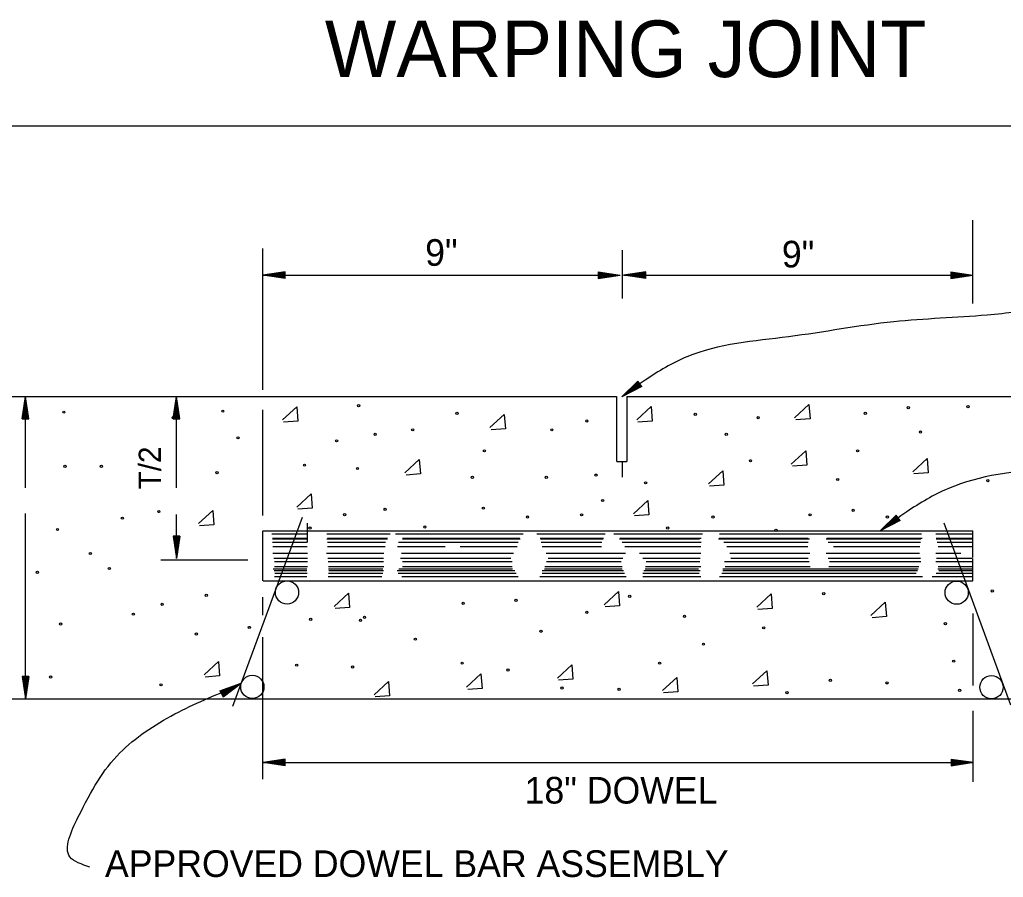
# Model space of a CAD drawing. Extents: x 1375738 to 1375905, y 380661 to 380875.
# Drawn here: x 1375749.18 to 1375765.86, y 380802.04 to 380816.58 of the extents above; entities that cross this region are included whole.
import ezdxf

# ---------------------------------------------------------------- set-up
doc = ezdxf.new("R2010")
doc.units = 0
doc.layers.add('R_Border', color=7, linetype='Continuous')
doc.layers.add('R_Draft', color=7, linetype='Continuous')

msp = doc.modelspace()

# ---------------------------------------------------------------- linework, layer by layer
at = {"layer": 'R_Border'}
msp.add_line((1375744.419, 380814.777), (1375786.095, 380814.777), dxfattribs=at)
at = {"layer": 'R_Draft'}
for p, q in [((1375765.343, 380811.767), (1375765.343, 380813.18)), ((1375753.306, 380810.302), (1375753.306, 380812.699)), ((1375759.401, 380811.851), (1375759.401, 380812.671)), ((1375753.682, 380812.303), (1375753.306, 380812.247)), ((1375753.682, 380812.19), (1375753.682, 380812.303)), ((1375758.988, 380812.303), (1375759.364, 380812.247)), ((1375758.988, 380812.303), (1375758.988, 380812.19)), ((1375759.797, 380812.303), (1375759.42, 380812.247)), ((1375759.797, 380812.303), (1375759.42, 380812.247)), ((1375759.797, 380812.19), (1375759.797, 380812.303)), ((1375759.797, 380812.19), (1375759.797, 380812.303)), ((1375764.966, 380812.303), (1375765.343, 380812.247)), ((1375764.966, 380812.303), (1375764.966, 380812.19)), ((1375753.306, 380812.247), (1375759.364, 380812.247)), ((1375753.682, 380812.19), (1375753.306, 380812.247)), ((1375753.682, 380812.294), (1375753.369, 380812.247)), ((1375753.682, 380812.2), (1375753.369, 380812.247)), ((1375753.682, 380812.284), (1375753.434, 380812.247)), ((1375753.682, 380812.21), (1375753.434, 380812.247)), ((1375753.682, 380812.275), (1375753.496, 380812.247)), ((1375753.682, 380812.219), (1375753.496, 380812.247)), ((1375753.682, 380812.265), (1375753.56, 380812.247)), ((1375753.682, 380812.229), (1375753.56, 380812.247)), ((1375753.682, 380812.255), (1375753.623, 380812.247)), ((1375753.682, 380812.238), (1375753.623, 380812.247)), ((1375758.988, 380812.294), (1375759.301, 380812.247)), ((1375758.988, 380812.284), (1375759.236, 380812.247)), ((1375758.988, 380812.275), (1375759.174, 380812.247)), ((1375758.988, 380812.265), (1375759.11, 380812.247)), ((1375758.988, 380812.255), (1375759.047, 380812.247)), ((1375758.988, 380812.19), (1375759.364, 380812.247)), ((1375758.988, 380812.228), (1375759.11, 380812.247)), ((1375758.988, 380812.21), (1375759.236, 380812.247)), ((1375758.988, 380812.2), (1375759.301, 380812.247)), ((1375758.988, 380812.219), (1375759.174, 380812.247)), ((1375758.988, 380812.238), (1375759.047, 380812.247)), ((1375759.42, 380812.247), (1375765.343, 380812.247)), ((1375759.797, 380812.19), (1375759.42, 380812.247)), ((1375759.797, 380812.19), (1375759.42, 380812.247)), ((1375759.797, 380812.294), (1375759.483, 380812.247)), ((1375759.797, 380812.294), (1375759.483, 380812.247)), ((1375759.797, 380812.2), (1375759.483, 380812.247)), ((1375759.797, 380812.2), (1375759.483, 380812.247)), ((1375759.797, 380812.284), (1375759.548, 380812.247)), ((1375759.797, 380812.284), (1375759.548, 380812.247)), ((1375759.797, 380812.21), (1375759.548, 380812.247)), ((1375759.797, 380812.21), (1375759.548, 380812.247)), ((1375759.797, 380812.275), (1375759.61, 380812.247)), ((1375759.797, 380812.275), (1375759.61, 380812.247)), ((1375759.797, 380812.219), (1375759.61, 380812.247)), ((1375759.797, 380812.219), (1375759.61, 380812.247)), ((1375759.797, 380812.265), (1375759.674, 380812.247)), ((1375759.797, 380812.265), (1375759.674, 380812.247)), ((1375759.797, 380812.229), (1375759.674, 380812.247)), ((1375759.797, 380812.229), (1375759.674, 380812.247)), ((1375759.797, 380812.255), (1375759.738, 380812.247)), ((1375759.797, 380812.255), (1375759.738, 380812.247)), ((1375759.797, 380812.238), (1375759.738, 380812.247)), ((1375759.797, 380812.238), (1375759.738, 380812.247)), ((1375764.966, 380812.294), (1375765.28, 380812.247)), ((1375764.966, 380812.284), (1375765.215, 380812.247)), ((1375764.966, 380812.275), (1375765.153, 380812.247)), ((1375764.966, 380812.265), (1375765.089, 380812.247)), ((1375764.966, 380812.255), (1375765.026, 380812.247)), ((1375764.966, 380812.19), (1375765.343, 380812.247)), ((1375764.966, 380812.228), (1375765.089, 380812.247)), ((1375764.966, 380812.21), (1375765.215, 380812.247)), ((1375764.966, 380812.2), (1375765.28, 380812.247)), ((1375764.966, 380812.219), (1375765.153, 380812.247)), ((1375764.966, 380812.238), (1375765.026, 380812.247)), ((1375759.665, 380810.448), (1375759.392, 380810.183)), ((1375759.731, 380810.356), (1375759.392, 380810.183)), ((1375759.671, 380810.441), (1375759.443, 380810.22)), ((1375759.726, 380810.364), (1375759.443, 380810.22)), ((1375759.676, 380810.432), (1375759.496, 380810.257)), ((1375759.72, 380810.371), (1375759.496, 380810.257)), ((1375759.682, 380810.425), (1375759.547, 380810.294)), ((1375759.714, 380810.379), (1375759.547, 380810.294)), ((1375759.688, 380810.417), (1375759.599, 380810.331)), ((1375759.709, 380810.387), (1375759.599, 380810.331)), ((1375759.693, 380810.409), (1375759.65, 380810.368)), ((1375759.703, 380810.395), (1375759.65, 380810.368)), ((1375759.731, 380810.356), (1375759.665, 380810.448)), ((1375747.021, 380810.189), (1375759.3, 380810.189)), ((1375749.223, 380809.813), (1375749.279, 380810.189)), ((1375749.336, 380809.813), (1375749.279, 380810.189)), ((1375749.279, 380808.642), (1375749.279, 380810.189)), ((1375751.786, 380809.813), (1375751.843, 380810.189)), ((1375751.843, 380808.642), (1375751.843, 380810.189)), ((1375751.9, 380809.813), (1375751.843, 380810.189)), ((1375759.305, 380809.089), (1375759.305, 380810.189)), ((1375759.477, 380810.189), (1375771.466, 380810.189)), ((1375759.479, 380809.089), (1375759.479, 380810.189)), ((1375749.232, 380809.813), (1375749.279, 380810.127)), ((1375749.242, 380809.813), (1375749.279, 380810.062)), ((1375749.251, 380809.813), (1375749.279, 380809.999)), ((1375749.326, 380809.813), (1375749.279, 380810.127)), ((1375749.316, 380809.813), (1375749.279, 380810.062)), ((1375749.307, 380809.813), (1375749.279, 380809.999)), ((1375751.796, 380809.813), (1375751.843, 380810.127)), ((1375751.806, 380809.813), (1375751.843, 380810.062)), ((1375751.815, 380809.813), (1375751.843, 380809.999)), ((1375751.89, 380809.813), (1375751.843, 380810.127)), ((1375751.88, 380809.813), (1375751.843, 380810.062)), ((1375751.871, 380809.813), (1375751.843, 380809.999)), ((1375749.223, 380809.813), (1375749.336, 380809.813)), ((1375749.261, 380809.813), (1375749.279, 380809.935)), ((1375749.27, 380809.813), (1375749.279, 380809.872)), ((1375749.298, 380809.813), (1375749.279, 380809.935)), ((1375749.288, 380809.813), (1375749.279, 380809.872)), ((1375751.786, 380809.813), (1375751.9, 380809.813)), ((1375751.825, 380809.813), (1375751.843, 380809.935)), ((1375751.835, 380809.813), (1375751.843, 380809.872)), ((1375751.862, 380809.813), (1375751.843, 380809.935)), ((1375751.852, 380809.813), (1375751.843, 380809.872)), ((1375753.306, 380808.173), (1375753.306, 380809.964)), ((1375759.305, 380809.089), (1375759.475, 380809.089)), ((1375759.401, 380808.819), (1375759.401, 380809.073)), ((1375749.279, 380805.063), (1375749.279, 380808.203)), ((1375751.843, 380807.442), (1375751.843, 380808.186)), ((1375753.97, 380808.136), (1375752.793, 380804.931)), ((1375764.044, 380808.175), (1375763.77, 380807.911)), ((1375764.05, 380808.168), (1375763.822, 380807.947)), ((1375764.055, 380808.16), (1375763.874, 380807.985)), ((1375764.06, 380808.153), (1375763.925, 380808.021)), ((1375764.066, 380808.145), (1375763.977, 380808.059)), ((1375764.072, 380808.137), (1375764.028, 380808.095)), ((1375764.11, 380808.084), (1375764.044, 380808.175)), ((1375754.06, 380807.72), (1375754.06, 380808.04)), ((1375764.11, 380808.084), (1375763.77, 380807.911)), ((1375764.104, 380808.091), (1375763.822, 380807.947)), ((1375764.098, 380808.099), (1375763.874, 380807.985)), ((1375764.093, 380808.107), (1375763.925, 380808.021)), ((1375764.088, 380808.115), (1375763.977, 380808.059)), ((1375764.082, 380808.122), (1375764.028, 380808.095)), ((1375764.849, 380808.047), (1375765.982, 380804.959)), ((1375751.786, 380807.819), (1375751.843, 380807.442)), ((1375751.9, 380807.819), (1375751.786, 380807.819)), ((1375751.796, 380807.819), (1375751.843, 380807.505)), ((1375751.806, 380807.819), (1375751.843, 380807.57)), ((1375751.815, 380807.819), (1375751.843, 380807.633)), ((1375751.824, 380807.819), (1375751.843, 380807.697)), ((1375751.835, 380807.819), (1375751.843, 380807.759)), ((1375751.9, 380807.819), (1375751.843, 380807.442)), ((1375751.861, 380807.819), (1375751.843, 380807.697)), ((1375751.88, 380807.819), (1375751.843, 380807.57)), ((1375751.89, 380807.819), (1375751.843, 380807.505)), ((1375751.871, 380807.819), (1375751.843, 380807.633)), ((1375751.852, 380807.819), (1375751.843, 380807.759)), ((1375753.306, 380807.066), (1375753.306, 380807.911)), ((1375753.312, 380807.911), (1375765.343, 380807.911)), ((1375753.456, 380807.859), (1375754.056, 380807.859)), ((1375754.392, 380807.859), (1375755.462, 380807.859)), ((1375755.554, 380807.859), (1375757.718, 380807.859)), ((1375757.95, 380807.859), (1375759.109, 380807.859)), ((1375759.258, 380807.859), (1375760.756, 380807.859)), ((1375761.046, 380807.859), (1375764.473, 380807.859)), ((1375764.714, 380807.859), (1375765.341, 380807.859)), ((1375765.343, 380807.461), (1375765.343, 380807.911)), ((1375753.466, 380807.788), (1375754.06, 380807.788)), ((1375753.466, 380807.774), (1375754.06, 380807.774)), ((1375753.466, 380807.717), (1375754.056, 380807.717)), ((1375753.477, 380807.647), (1375754.056, 380807.647)), ((1375754.392, 380807.774), (1375755.42, 380807.774)), ((1375754.399, 380807.788), (1375755.42, 380807.788)), ((1375754.399, 380807.717), (1375755.385, 380807.717)), ((1375754.399, 380807.647), (1375755.378, 380807.647)), ((1375755.59, 380807.647), (1375756.396, 380807.647)), ((1375755.604, 380807.717), (1375757.632, 380807.717)), ((1375755.675, 380807.788), (1375757.66, 380807.788)), ((1375755.675, 380807.774), (1375757.668, 380807.774)), ((1375756.65, 380807.647), (1375757.618, 380807.647)), ((1375758.007, 380807.788), (1375759.081, 380807.788)), ((1375758.014, 380807.774), (1375759.074, 380807.774)), ((1375758.021, 380807.717), (1375759.052, 380807.717)), ((1375758.042, 380807.647), (1375759.046, 380807.647)), ((1375759.35, 380807.774), (1375760.707, 380807.774)), ((1375759.357, 380807.788), (1375760.735, 380807.788)), ((1375759.399, 380807.717), (1375760.735, 380807.717)), ((1375759.441, 380807.647), (1375760.728, 380807.647)), ((1375761.031, 380807.774), (1375762.572, 380807.774)), ((1375761.039, 380807.788), (1375762.551, 380807.788)), ((1375761.123, 380807.717), (1375762.551, 380807.717)), ((1375761.173, 380807.647), (1375762.544, 380807.647)), ((1375762.855, 380807.774), (1375764.459, 380807.774)), ((1375762.869, 380807.788), (1375764.481, 380807.788)), ((1375762.89, 380807.717), (1375764.452, 380807.717)), ((1375762.982, 380807.647), (1375764.445, 380807.647)), ((1375764.721, 380807.788), (1375765.341, 380807.788)), ((1375764.721, 380807.774), (1375765.341, 380807.774)), ((1375764.735, 380807.717), (1375765.341, 380807.717)), ((1375764.756, 380807.647), (1375765.341, 380807.647)), ((1375753.474, 380807.533), (1375754.06, 380807.533)), ((1375754.385, 380807.533), (1375755.357, 380807.533)), ((1375755.653, 380807.533), (1375757.555, 380807.533)), ((1375758.106, 380807.533), (1375759.455, 380807.533)), ((1375759.688, 380807.533), (1375760.728, 380807.533)), ((1375761.222, 380807.533), (1375762.58, 380807.533)), ((1375762.855, 380807.533), (1375764.438, 380807.533)), ((1375764.714, 380807.533), (1375765.138, 380807.533)), ((1375751.576, 380807.418), (1375753.049, 380807.418)), ((1375753.494, 380807.449), (1375754.06, 380807.449)), ((1375753.502, 380807.392), (1375754.063, 380807.392)), ((1375753.502, 380807.308), (1375754.063, 380807.308)), ((1375754.406, 380807.449), (1375755.35, 380807.449)), ((1375754.41, 380807.392), (1375755.35, 380807.392)), ((1375754.417, 380807.308), (1375755.357, 380807.308)), ((1375755.639, 380807.449), (1375757.512, 380807.449)), ((1375755.675, 380807.392), (1375757.533, 380807.392)), ((1375755.675, 380807.308), (1375757.533, 380807.308)), ((1375758.084, 380807.308), (1375759.399, 380807.308)), ((1375758.113, 380807.392), (1375759.378, 380807.392)), ((1375758.141, 380807.449), (1375759.406, 380807.449)), ((1375759.745, 380807.449), (1375760.721, 380807.449)), ((1375759.795, 380807.308), (1375760.728, 380807.308)), ((1375759.802, 380807.392), (1375760.714, 380807.392)), ((1375761.131, 380807.392), (1375762.565, 380807.392)), ((1375761.145, 380807.308), (1375762.586, 380807.308)), ((1375761.237, 380807.449), (1375762.551, 380807.449)), ((1375762.89, 380807.449), (1375764.452, 380807.449)), ((1375762.898, 380807.308), (1375764.424, 380807.308)), ((1375762.912, 380807.392), (1375764.459, 380807.392)), ((1375764.714, 380807.392), (1375765.341, 380807.392)), ((1375764.728, 380807.449), (1375765.329, 380807.449)), ((1375764.756, 380807.308), (1375765.329, 380807.308)), ((1375765.343, 380807.066), (1375765.343, 380807.441)), ((1375753.48, 380807.265), (1375754.053, 380807.265)), ((1375753.498, 380807.237), (1375754.053, 380807.237)), ((1375753.505, 380807.138), (1375754.053, 380807.138)), ((1375753.508, 380807.195), (1375754.056, 380807.195)), ((1375754.413, 380807.138), (1375755.322, 380807.138)), ((1375754.417, 380807.195), (1375755.342, 380807.195)), ((1375754.42, 380807.265), (1375755.342, 380807.265)), ((1375754.424, 380807.237), (1375755.35, 380807.237)), ((1375755.583, 380807.237), (1375757.576, 380807.237)), ((1375755.597, 380807.195), (1375757.597, 380807.195)), ((1375755.612, 380807.265), (1375757.54, 380807.265)), ((1375755.661, 380807.138), (1375757.632, 380807.138)), ((1375758, 380807.138), (1375759.463, 380807.138)), ((1375758.042, 380807.237), (1375759.42, 380807.237)), ((1375758.042, 380807.195), (1375759.434, 380807.195)), ((1375758.078, 380807.265), (1375759.399, 380807.265)), ((1375759.745, 380807.195), (1375760.7, 380807.195)), ((1375759.745, 380807.138), (1375760.728, 380807.138)), ((1375759.766, 380807.237), (1375760.721, 380807.237)), ((1375759.788, 380807.265), (1375760.692, 380807.265)), ((1375761.046, 380807.138), (1375764.488, 380807.138)), ((1375761.088, 380807.195), (1375764.381, 380807.195)), ((1375761.102, 380807.265), (1375764.417, 380807.265)), ((1375761.102, 380807.237), (1375764.403, 380807.237)), ((1375764.65, 380807.138), (1375765.322, 380807.138)), ((1375764.721, 380807.195), (1375765.343, 380807.195)), ((1375764.749, 380807.265), (1375765.341, 380807.265)), ((1375764.763, 380807.237), (1375765.35, 380807.237)), ((1375753.312, 380807.066), (1375765.343, 380807.066)), ((1375753.306, 380806.481), (1375753.306, 380806.787)), ((1375765.35, 380805.291), (1375765.35, 380806.508)), ((1375753.306, 380804.349), (1375753.306, 380806.109)), ((1375749.223, 380805.439), (1375749.279, 380805.063)), ((1375749.336, 380805.439), (1375749.223, 380805.439)), ((1375749.232, 380805.439), (1375749.279, 380805.126)), ((1375749.242, 380805.439), (1375749.279, 380805.191)), ((1375749.251, 380805.439), (1375749.279, 380805.253)), ((1375749.261, 380805.439), (1375749.279, 380805.317)), ((1375749.27, 380805.439), (1375749.279, 380805.38)), ((1375749.336, 380805.439), (1375749.279, 380805.063)), ((1375749.297, 380805.439), (1375749.279, 380805.317)), ((1375749.316, 380805.439), (1375749.279, 380805.191)), ((1375749.326, 380805.439), (1375749.279, 380805.126)), ((1375749.307, 380805.439), (1375749.279, 380805.253)), ((1375749.288, 380805.439), (1375749.279, 380805.38)), ((1375752.576, 380805.197), (1375752.935, 380805.326)), ((1375752.63, 380805.098), (1375752.935, 380805.326)), ((1375752.576, 380805.197), (1375752.63, 380805.098)), ((1375752.581, 380805.189), (1375752.879, 380805.296)), ((1375752.586, 380805.181), (1375752.822, 380805.265)), ((1375752.59, 380805.173), (1375752.767, 380805.236)), ((1375752.595, 380805.164), (1375752.711, 380805.205)), ((1375752.599, 380805.155), (1375752.656, 380805.176)), ((1375752.608, 380805.139), (1375752.656, 380805.176)), ((1375752.612, 380805.131), (1375752.711, 380805.205)), ((1375752.616, 380805.123), (1375752.767, 380805.236)), ((1375752.621, 380805.114), (1375752.822, 380805.265)), ((1375752.626, 380805.106), (1375752.879, 380805.296)), ((1375747.021, 380805.063), (1375771.466, 380805.063)), ((1375765.35, 380803.653), (1375765.35, 380804.861)), ((1375753.306, 380803.703), (1375753.306, 380804.473)), ((1375753.306, 380803.983), (1375764.028, 380803.983)), ((1375753.686, 380804.039), (1375753.31, 380803.983)), ((1375753.686, 380803.926), (1375753.31, 380803.983)), ((1375753.686, 380804.03), (1375753.373, 380803.983)), ((1375753.686, 380803.936), (1375753.373, 380803.983)), ((1375753.686, 380804.02), (1375753.438, 380803.983)), ((1375753.686, 380803.946), (1375753.438, 380803.983)), ((1375753.686, 380804.011), (1375753.5, 380803.983)), ((1375753.686, 380803.955), (1375753.5, 380803.983)), ((1375753.686, 380804.001), (1375753.564, 380803.983)), ((1375753.686, 380803.965), (1375753.564, 380803.983)), ((1375753.686, 380803.991), (1375753.627, 380803.983)), ((1375753.686, 380803.974), (1375753.627, 380803.983)), ((1375753.686, 380803.926), (1375753.686, 380804.039)), ((1375763.961, 380803.983), (1375765.35, 380803.983)), ((1375764.976, 380804.042), (1375765.353, 380803.986)), ((1375764.976, 380804.042), (1375764.976, 380803.929)), ((1375764.976, 380804.033), (1375765.29, 380803.986)), ((1375764.976, 380804.023), (1375765.225, 380803.986)), ((1375764.976, 380804.013), (1375765.163, 380803.986)), ((1375764.976, 380804.004), (1375765.099, 380803.986)), ((1375764.976, 380803.995), (1375765.036, 380803.986)), ((1375764.976, 380803.929), (1375765.353, 380803.986)), ((1375764.976, 380803.967), (1375765.099, 380803.986)), ((1375764.976, 380803.949), (1375765.225, 380803.986)), ((1375764.976, 380803.939), (1375765.29, 380803.986)), ((1375764.976, 380803.958), (1375765.163, 380803.986)), ((1375764.976, 380803.977), (1375765.036, 380803.986))]:
    msp.add_line(p, q, dxfattribs=at)
for points in [[(1375753.638, 380809.792), (1375753.88, 380810.016), (1375753.9, 380809.773), (1375753.656, 380809.754)], [(1375759.645, 380809.792), (1375759.888, 380810.017), (1375759.906, 380809.773), (1375759.664, 380809.755)], [(1375762.321, 380809.829), (1375762.564, 380810.054), (1375762.583, 380809.81), (1375762.339, 380809.792)], [(1375757.156, 380809.661), (1375757.399, 380809.885), (1375757.418, 380809.641), (1375757.175, 380809.623)], [(1375762.264, 380809.043), (1375762.508, 380809.268), (1375762.526, 380809.025), (1375762.284, 380809.006)], [(1375764.323, 380808.913), (1375764.566, 380809.137), (1375764.585, 380808.893), (1375764.342, 380808.875)], [(1375755.715, 380808.893), (1375755.958, 380809.118), (1375755.976, 380808.875), (1375755.734, 380808.856)], [(1375760.861, 380808.707), (1375761.104, 380808.931), (1375761.123, 380808.688), (1375760.88, 380808.669)], [(1375753.88, 380808.313), (1375754.124, 380808.538), (1375754.143, 380808.294), (1375753.9, 380808.276)], [(1375759.588, 380808.201), (1375759.832, 380808.425), (1375759.851, 380808.182), (1375759.608, 380808.164)], [(1375752.215, 380808.033), (1375752.458, 380808.257), (1375752.477, 380808.013), (1375752.234, 380807.995)], [(1375754.512, 380806.63), (1375754.756, 380806.855), (1375754.774, 380806.611), (1375754.531, 380806.593)], [(1375759.092, 380806.658), (1375759.335, 380806.883), (1375759.354, 380806.639), (1375759.111, 380806.621)], [(1375761.678, 380806.616), (1375761.922, 380806.841), (1375761.94, 380806.597), (1375761.697, 380806.579)], [(1375763.615, 380806.475), (1375763.858, 380806.699), (1375763.877, 380806.456), (1375763.634, 380806.437)], [(1375752.309, 380805.469), (1375752.552, 380805.693), (1375752.571, 380805.45), (1375752.327, 380805.431)], [(1375758.3, 380805.414), (1375758.544, 380805.639), (1375758.562, 380805.396), (1375758.319, 380805.377)], [(1375756.76, 380805.259), (1375757.003, 380805.484), (1375757.022, 380805.24), (1375756.778, 380805.222)], [(1375761.608, 380805.315), (1375761.851, 380805.54), (1375761.87, 380805.297), (1375761.626, 380805.278)], [(1375755.191, 380805.132), (1375755.434, 380805.357), (1375755.453, 380805.113), (1375755.21, 380805.095)], [(1375760.081, 380805.203), (1375760.324, 380805.427), (1375760.343, 380805.184), (1375760.1, 380805.165)]]:
    msp.add_lwpolyline(points, dxfattribs=at)
for centre, radius in [((1375754.929, 380810.035), 0.0188), ((1375764.248, 380809.998), 0.0188), ((1375765.259, 380810.016), 0.0188), ((1375749.932, 380809.923), 0.0188), ((1375751.785, 380809.829), 0.0188), ((1375752.627, 380809.941), 0.0188), ((1375756.595, 380809.904), 0.0188), ((1375760.637, 380809.885), 0.0188), ((1375761.703, 380809.829), 0.0188), ((1375763.519, 380809.904), 0.0188), ((1375755.846, 380809.623), 0.0188), ((1375758.204, 380809.623), 0.0188), ((1375758.798, 380809.775), 0.0188), ((1375752.883, 380809.488), 0.0188), ((1375755.21, 380809.549), 0.0188), ((1375761.161, 380809.549), 0.0188), ((1375764.454, 380809.586), 0.0188), ((1375754.556, 380809.437), 0.0188), ((1375757.062, 380809.268), 0.0188), ((1375763.388, 380809.268), 0.0188), ((1375749.951, 380809.006), 0.0188), ((1375750.568, 380809.006), 0.0188), ((1375754.012, 380809.024), 0.0188), ((1375754.91, 380808.968), 0.0188), ((1375761.572, 380809.099), 0.0188), ((1375752.528, 380808.896), 0.0188), ((1375756.857, 380808.818), 0.0188), ((1375758.11, 380808.818), 0.0188), ((1375758.953, 380808.856), 0.0188), ((1375759.794, 380808.725), 0.0188), ((1375763.051, 380808.781), 0.0188), ((1375765.596, 380808.762), 0.0188), ((1375757.044, 380808.295), 0.0188), ((1375759.065, 380808.425), 0.0188), ((1375750.924, 380808.126), 0.0188), ((1375751.542, 380808.238), 0.0188), ((1375754.691, 380808.186), 0.0188), ((1375755.378, 380808.276), 0.0188), ((1375757.792, 380808.145), 0.0188), ((1375758.709, 380808.182), 0.0188), ((1375760.936, 380808.145), 0.0188), ((1375762.583, 380808.182), 0.0188), ((1375763.313, 380808.257), 0.0188), ((1375763.893, 380808.145), 0.0188), ((1375754.105, 380807.958), 0.0188), ((1375756.052, 380807.976), 0.0188), ((1375760.169, 380807.958), 0.0188), ((1375749.824, 380807.933), 0.0188), ((1375762.003, 380807.92), 0.0188), ((1375750.381, 380807.527), 0.0188), ((1375749.483, 380807.209), 0.0188), ((1375750.703, 380807.273), 0.0188), ((1375753.715, 380806.866), 0.197), ((1375765.068, 380806.863), 0.197), ((1375752.346, 380806.816), 0.0188), ((1375759.525, 380806.8), 0.0188), ((1375762.813, 380806.846), 0.0188), ((1375765.671, 380806.891), 0.0188), ((1375751.598, 380806.666), 0.0188), ((1375756.702, 380806.682), 0.0188), ((1375757.598, 380806.733), 0.0188), ((1375751.111, 380806.498), 0.0188), ((1375758.798, 380806.53), 0.0188), ((1375760.454, 380806.462), 0.0188), ((1375749.876, 380806.33), 0.0188), ((1375754.116, 380806.412), 0.0188), ((1375754.961, 380806.395), 0.0188), ((1375755.029, 380806.445), 0.0188), ((1375764.877, 380806.337), 0.0188), ((1375752.178, 380806.161), 0.0188), ((1375753.076, 380806.273), 0.0188), ((1375758.02, 380806.209), 0.0188), ((1375761.796, 380806.266), 0.0188), ((1375755.891, 380806.074), 0.0188), ((1375760.775, 380805.989), 0.0188), ((1375753.88, 380805.634), 0.0188), ((1375756.685, 380805.668), 0.0188), ((1375760.032, 380805.668), 0.0188), ((1375765.018, 380805.701), 0.0188), ((1375754.826, 380805.601), 0.0188), ((1375757.462, 380805.55), 0.0188), ((1375749.708, 380805.431), 0.0188), ((1375751.579, 380805.3), 0.0188), ((1375753.127, 380805.265), 0.197), ((1375762.926, 380805.376), 0.0188), ((1375763.887, 380805.333), 0.0188), ((1375765.658, 380805.26), 0.197), ((1375758.375, 380805.246), 0.0188), ((1375759.345, 380805.225), 0.0188), ((1375762.19, 380805.169), 0.0188), ((1375765.117, 380805.206), 0.0188)]:
    msp.add_circle(centre, radius, dxfattribs=at)
for points in [[(1375766.572, 380811.682), (1375765.583, 380811.569), (1375764, 380811.455), (1375762.219, 380811.201), (1375760.494, 380810.862), (1375759.788, 380810.466), (1375759.392, 380810.183)], [(1375772.536, 380808.703), (1375772.472, 380808.703), (1375768.969, 380808.978), (1375766.652, 380808.967), (1375764.927, 380808.628), (1375764.22, 380808.232), (1375763.824, 380807.949)], [(1375750.374, 380802.211), (1375750.035, 380802.381), (1375750.176, 380803.059), (1375750.88, 380804.145), (1375751.811, 380804.806), (1375752.826, 380805.258)]]:
    msp.add_spline(points, degree=3, dxfattribs=at)

# ---------------------------------------------------------------- texts
for s, height, p in [('WARPING JOINT', 0.96, (1375754.356, 380815.604)), ('9"', 0.4516, (1375756.057, 380812.405)), ('9"', 0.4516, (1375762.104, 380812.377)), ('18" DOWEL', 0.4516, (1375757.743, 380803.287)), ('APPROVED DOWEL BAR ASSEMBLY', 0.45163, (1375750.629, 380802.042))]:
    msp.add_text(s, height=height, dxfattribs=at).set_placement(p)
msp.add_text('T/2', height=0.3764, rotation=90, dxfattribs=at).set_placement((1375751.577, 380808.614))

doc.saveas('drawing.dxf')
